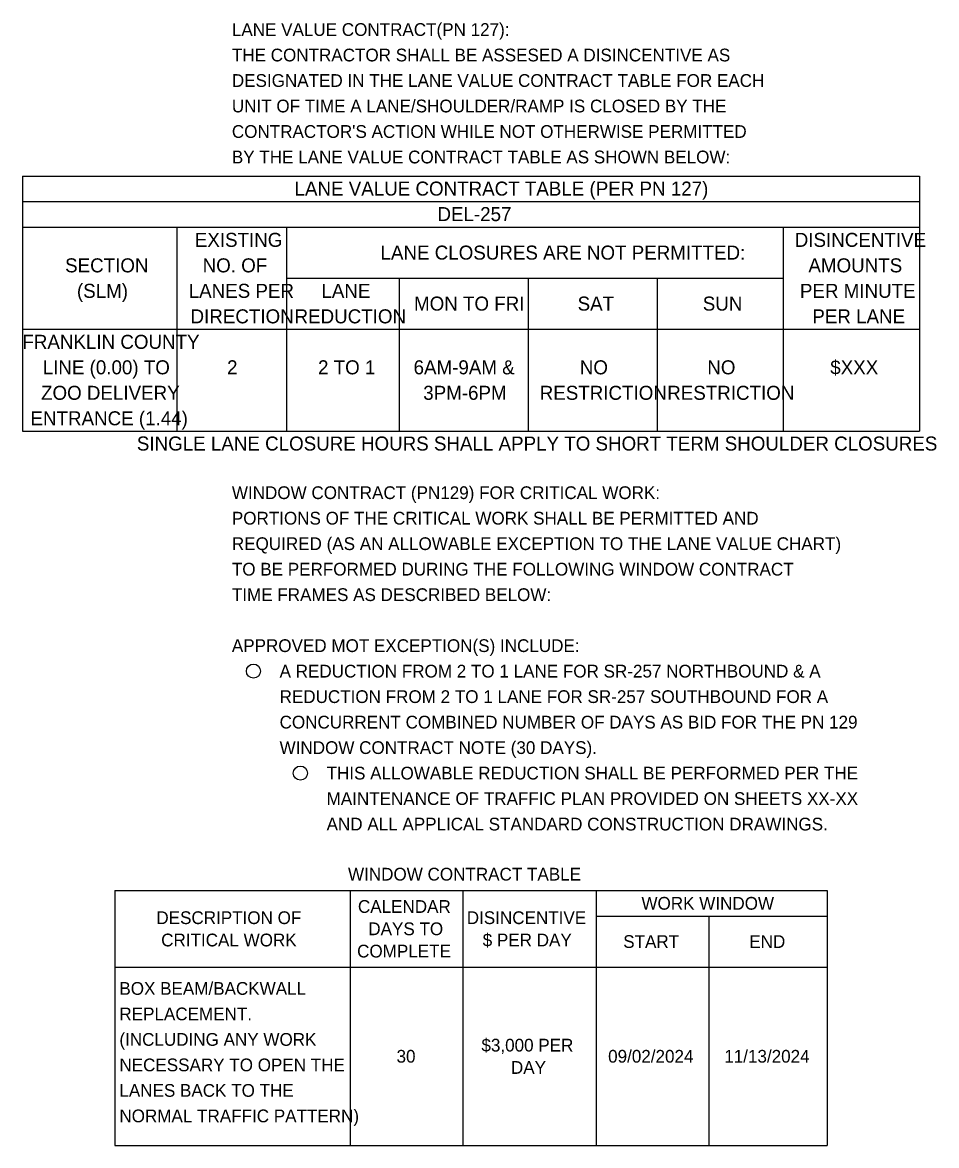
# Model space of a CAD drawing. Extents: x -15.6 to 56.6, y 0 to 56.8.
# Drawn here: x 46.56 to 56.6, y 9.67 to 22.01 of the extents above; entities that cross this region are included whole.
import ezdxf

# ---------------------------------------------------------------- set-up
doc = ezdxf.new("R2010")
doc.units = 0
doc.layers.add('SH_Data', color=7, linetype='Continuous')
doc.layers.add('SH_Text', color=7, linetype='Continuous')

msp = doc.modelspace()

# ---------------------------------------------------------------- linework, layer by layer
at = {"layer": 'SH_Data'}
for p, q in [((46.564, 20.319), (56.413, 20.319)), ((46.564, 20.319), (46.564, 17.519)), ((56.413, 20.319), (56.413, 17.519)), ((46.564, 20.039), (56.413, 20.039)), ((46.564, 19.759), (56.413, 19.759)), ((48.26, 19.759), (48.26, 17.519)), ((49.463, 19.759), (49.463, 17.519)), ((54.915, 19.759), (54.915, 17.519)), ((49.463, 19.199), (54.915, 19.199)), ((50.698, 19.199), (50.698, 17.519)), ((52.115, 19.199), (52.115, 17.519)), ((53.531, 19.199), (53.531, 17.519)), ((46.564, 18.639), (56.413, 18.639)), ((46.564, 17.519), (56.413, 17.519))]:
    msp.add_line(p, q, dxfattribs=at)
at = {"layer": 'SH_Text'}
for p, q in [((47.577, 12.472), (55.4, 12.472)), ((47.577, 12.472), (47.577, 9.672)), ((50.163, 12.472), (50.163, 9.672)), ((51.398, 12.472), (51.398, 9.672)), ((52.864, 12.472), (52.864, 9.672)), ((55.4, 12.472), (55.4, 9.672)), ((52.864, 12.192), (55.4, 12.192)), ((54.099, 12.192), (54.099, 9.672)), ((47.577, 11.632), (55.4, 11.632)), ((47.577, 9.672), (55.4, 9.672))]:
    msp.add_line(p, q, dxfattribs=at)
for centre in [(49.1, 14.882), (49.615, 13.762)]:
    msp.add_circle(centre, 0.0775, dxfattribs=at)

# ---------------------------------------------------------------- texts
at = {"layer": 'SH_Data'}
for s, height, p in [('LANE VALUE CONTRACT TABLE (PER PN 127)', 0.154, (49.551, 20.105)), ('DEL-257', 0.154, (51.12, 19.825)), ('EXISTING', 0.154, (48.456, 19.542)), ('DISINCENTIVE', 0.154, (55.043, 19.542)), ('LANE CLOSURES ARE NOT PERMITTED:', 0.154, (50.495, 19.402)), ('SECTION', 0.154, (47.032, 19.262)), ('NO. OF', 0.154, (48.542, 19.262)), ('AMOUNTS', 0.154, (55.193, 19.262)), ('(SLM)', 0.154, (47.162, 18.982)), ('LANES PER', 0.154, (48.389, 18.982)), ('LANE', 0.154, (49.846, 18.982)), ('PER MINUTE', 0.154, (55.1, 18.982)), ('MON TO FRI', 0.154, (50.863, 18.842)), ('SAT', 0.154, (52.659, 18.842)), ('SUN', 0.154, (54.033, 18.842)), (' DIRECTION', 0.154, (48.352, 18.702)), ('REDUCTION', 0.154, (49.551, 18.702)), ('PER LANE', 0.154, (55.236, 18.702)), ('FRANKLIN COUNTY', 0.154, (46.563, 18.422)), ('LINE (0.00) TO', 0.154, (46.786, 18.142)), ('2', 0.154, (48.81, 18.142)), ('2 TO 1', 0.154, (49.809, 18.142)), ('6AM-9AM &', 0.154, (50.858, 18.142)), ('NO', 0.154, (52.683, 18.142)), ('NO', 0.154, (54.083, 18.142)), ('$XXX', 0.154, (55.433, 18.142)), ('ZOO DELIVERY', 0.154, (46.768, 17.862)), ('3PM-6PM', 0.154, (50.964, 17.862)), ('RESTRICTION', 0.154, (52.243, 17.862)), ('RESTRICTION', 0.154, (53.643, 17.862)), ('ENTRANCE (1.44)', 0.154, (46.652, 17.582)), ('SINGLE LANE CLOSURE HOURS SHALL APPLY TO SHORT TERM SHOULDER CLOSURES', 0.154, (47.82, 17.305)), ('WINDOW CONTRACT TABLE', 0.14, (50.138, 12.582)), ('BOX BEAM/BACKWALL ', 0.14, (47.628, 11.327)), ('REPLACEMENT.', 0.14, (47.628, 11.047)), ('(INCLUDING ANY WORK', 0.14, (47.628, 10.767)), ('NECESSARY TO OPEN THE', 0.14, (47.628, 10.487)), ('LANES BACK TO THE ', 0.14, (47.628, 10.207)), ('NORMAL TRAFFIC PATTERN)', 0.14, (47.628, 9.927))]:
    msp.add_text(s, height=height, dxfattribs=at).set_placement(p)
at = {"layer": 'SH_Text'}
for s, p in [('LANE VALUE CONTRACT(PN 127):', (48.863, 21.859)), ('THE CONTRACTOR SHALL BE ASSESED A DISINCENTIVE AS ', (48.863, 21.579)), ('DESIGNATED IN THE LANE VALUE CONTRACT TABLE FOR EACH ', (48.863, 21.299)), ('UNIT OF TIME A LANE/SHOULDER/RAMP IS CLOSED BY THE', (48.863, 21.019)), ("CONTRACTOR'S ACTION WHILE NOT OTHERWISE PERMITTED", (48.863, 20.739)), ('BY THE LANE VALUE CONTRACT TABLE AS SHOWN BELOW:', (48.863, 20.459)), ('WINDOW CONTRACT (PN129) FOR CRITICAL WORK:', (48.863, 16.772)), ('PORTIONS OF THE CRITICAL WORK SHALL BE PERMITTED AND ', (48.863, 16.492)), ('REQUIRED (AS AN ALLOWABLE EXCEPTION TO THE LANE VALUE CHART) ', (48.863, 16.212)), ('TO BE PERFORMED DURING THE FOLLOWING WINDOW CONTRACT ', (48.863, 15.932)), ('TIME FRAMES AS DESCRIBED BELOW:', (48.863, 15.652)), ('APPROVED MOT EXCEPTION(S) INCLUDE: ', (48.863, 15.092)), ('A REDUCTION FROM 2 TO 1 LANE FOR SR-257 NORTHBOUND & A ', (49.387, 14.812)), ('REDUCTION FROM 2 TO 1 LANE FOR SR-257 SOUTHBOUND FOR A ', (49.387, 14.532)), ('CONCURRENT COMBINED NUMBER OF DAYS AS BID FOR THE PN 129 ', (49.387, 14.252)), ('WINDOW CONTRACT NOTE (30 DAYS).', (49.387, 13.972)), ('THIS ALLOWABLE REDUCTION SHALL BE PERFORMED PER THE', (49.903, 13.692)), ('MAINTENANCE OF TRAFFIC PLAN PROVIDED ON SHEETS XX-XX', (49.903, 13.412)), ('AND ALL APPLICAL STANDARD CONSTRUCTION DRAWINGS.', (49.903, 13.132)), ('CALENDAR ', (50.247, 12.227)), ('WORK WINDOW', (53.36, 12.262)), ('DESCRIPTION OF ', (48.034, 12.104)), ('DISINCENTIVE ', (51.442, 12.104)), ('DAYS TO ', (50.361, 11.982)), ('CRITICAL WORK', (48.087, 11.859)), ('$ PER DAY', (51.617, 11.859)), ('START', (53.16, 11.842)), ('END', (54.544, 11.842)), ('COMPLETE', (50.238, 11.737)), ('$3,000 PER ', (51.603, 10.704)), ('30', (50.671, 10.582)), ('09/02/2024', (52.994, 10.582)), ('11/13/2024', (54.269, 10.582)), ('DAY', (51.927, 10.459))]:
    msp.add_text(s, height=0.14, dxfattribs=at).set_placement(p)

doc.saveas('drawing.dxf')
